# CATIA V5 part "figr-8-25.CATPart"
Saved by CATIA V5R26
Part number: Part1
Bounding box of the stored display mesh (mm): x -50 to 50, y -62.5 to 62.5, z 0 to 10
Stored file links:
  D:\_Deepak\CATIA\CATIA V5-6R2016_Deepak\Resources\Part files\Partfiles\c08_catia_v5_6r2016_prt\figr-8-25.CATPart
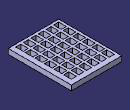
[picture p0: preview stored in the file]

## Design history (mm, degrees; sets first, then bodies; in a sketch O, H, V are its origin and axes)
Body1 (main body)
  Sketch1 on xy-plane, origin (0, 0, 0), H (1, 0, 0), V (0, 1, 0)
    line L1 (-50, 62.5) -> (50, 62.5)
    line L2 (50, 62.5) -> (50, -62.5)
    line L3 (50, -62.5) -> (-50, -62.5)
    line L4 (-50, -62.5) -> (-50, 62.5)
    axis line L5 (50, -62.5) -> (-50, 62.5)
    length L3 = 100
    length L2 = 125
    horizontal: L1 H, L3 H
    vertical: L2 V, L4 V
    midpoint: O L5
  Pad1: profile Sketch1, direction (0, 0, 1), length 10
  Sketch2 on face of Pad1, origin (0, 0, 10), H (1, 0, 0), V (0, 1, 0)
    line L1 (40, -57.5) -> (30, -57.5)
    line L2 (30, -57.5) -> (30, -42.5)
    line L3 (30, -42.5) -> (40, -42.5)
    line L4 (40, -42.5) -> (40, -57.5)
    reference projected line E1 (-50, -62.5) -> (50, -62.5) from edge [face of Pad1 | face of Pad1]
    reference projected line E2 (50, -62.5) -> (50, 62.5) from edge [face of Pad1 | face of Pad1]
    length L1 = 10
    length L4 = 15
    distance L1 E1 = 5
    distance L4 E2 = 10
    horizontal: L1 H, L3 H
    vertical: L2 V, L4 V
  Pocket1: profile Sketch2, direction (0, 0, -1), through (limit type 3)
  RectPattern1: of Pocket1, direction 1 instances 6, spacing 19, along edge [face of Pad1 | face of Pad1], direction 2 instances 6, spacing 15, along edge [face of Pad1 | face of Pad1] reversed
